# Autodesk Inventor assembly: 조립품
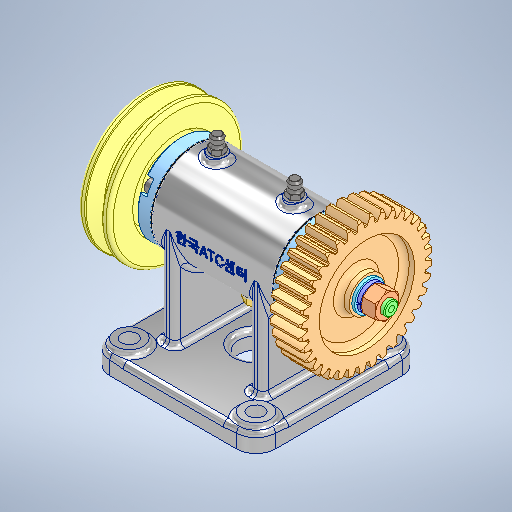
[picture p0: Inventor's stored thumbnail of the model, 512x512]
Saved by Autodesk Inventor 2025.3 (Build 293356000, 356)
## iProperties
Created: 2025-10
Part Number: 조립품
Document SubType Name: Assembly
Designer: USER
Author: USER
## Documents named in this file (17)
- C:\Users\USER\Desktop\751003V1013\조립품.iam
- C:\Users\USER\Desktop\751003V1013\본체.ipt
- C:\Users\USER\Desktop\751003V1013\깊은 홈 볼 베어링 6002\깊은 홈 볼 베어링 6002\깊은 홈 볼 베어링 6002.ipt
- C:\Users\USER\Desktop\751003V1013\축\축\축.ipt
- C:\Users\USER\Desktop\751003V1013\가스켓\가스켓\가스켓.ipt
- C:\Users\USER\Desktop\751003V1013\커버\커버\커버.ipt
- C:\Users\USER\Desktop\751003V1013\오일 실 15 25 4\오일 실 15 25 4\오일 실 15 25 4.ipt
- C:\Users\USER\Desktop\751003V1013\6각 머리 볼트 M6x0.75x8\6각 머리 볼트 M6x0.75x8\6각 머리 볼트 M6x0.75x8.ipt
- C:\Users\USER\Desktop\751003V1013\6각 구멍붙이 볼트 M4x10\6각 구멍붙이 볼트 M4x10\6각 구멍붙이 볼트 M4x10.ipt
- C:\Users\USER\Desktop\751003V1013\평행 키 3x3x12\평행 키 3x3x12\평행 키 3x3x12.ipt
- C:\Users\USER\Desktop\751003V1013\스퍼 기어\스퍼 기어\스퍼 기어.ipt
- C:\Users\USER\Desktop\751003V1013\V 벨트 풀리\V 벨트 풀리\V 벨트 풀리.ipt
- C:\Users\USER\Desktop\751003V1013\평 와셔 M8\평 와셔 M8\평 와셔 M8.ipt
- C:\Users\USER\Desktop\751003V1013\스프링 와셔 M8\스프링 와셔 M8\스프링 와셔 M8.ipt
- C:\Users\USER\Desktop\751003V1013\6각 너트 M8x1\6각 너트 M8x1\6각 너트 M8x1.ipt
- C:\Users\USER\Desktop\751003V1013\그리스 니플 M6x0.75\그리스 니플 M6x0.75\그리스 니플 M6x0.75.ipt
- C:\Users\USER\Desktop\751003V1013\실링\실링\실링.ipt
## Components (14 placed, 6 different names)
1. 가스켓:1
2. 가스켓:2
3. 6각 구멍붙이 볼트 M4x10:1
4. 6각 구멍붙이 볼트 M4x10:2
5. 6각 구멍붙이 볼트 M4x10:3
6. 6각 구멍붙이 볼트 M4x10:4
7. 6각 구멍붙이 볼트 M4x10:5
8. 6각 구멍붙이 볼트 M4x10:6
9. V 벨트 풀리:1
10. 6각 너트 M8x1:1
11. 6각 너트 M8x1:2
12. 그리스 니플 M6x0.75:1
13. 그리스 니플 M6x0.75:2
14. 6각 머리 볼트 M6x0.75x8:1
